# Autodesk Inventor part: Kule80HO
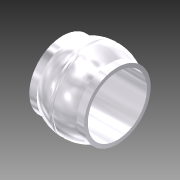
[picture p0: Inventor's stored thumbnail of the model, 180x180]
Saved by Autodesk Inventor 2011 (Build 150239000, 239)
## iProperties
Created: 2010-11
Document SubType Name: Modeling
Designer: tribel
Density: 1 g/cm^3
Author: tribel
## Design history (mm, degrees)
sketch "Sketch1"
  geometry: L1 (-51.8, 0)-(51.8, 0) reference; L2 (0, -11.888)-(0, 71.331) reference; L3 (-37, 45)-(-26.935, 45); L4 (-37, 45)-(-37, 0); L5 (-3, 0)-(-3, 52.359); L6 (-37, 40)-(-3, 40); L7 (37, 45)-(26.935, 45); L8 (37, 45)-(37, 0); L9 (37, 40)-(3, 40); L10 (3, 0)-(3, 52.359); L11 (-3, 40)-(3, 40); A1 r 7.692 centre (0, 59.442) between (-3, 52.359) and (3, 52.359); A2 r 52.445 centre (0, 0) between (26.935, 45) and (3, 52.359); A3 r 52.445 centre (0, 0) between (-3, 52.359) and (-26.935, 45)
  constraints: 18 end point, 7 symmetric about line, 6 point on circle, 6 point on line, 4 perpendicular, 3 centre point, 1 parallel
  dimensions: "d1" = 37 distance between parallel lines of L4 L2; "d2" = 3 distance between parallel lines of L5 L2; "d3" = 90 diameter of L3 L1; "d4" = 103.5 dimension on A1 L1; "d5" = 80 diameter of L9 L1; "d7" = 52.445 radius of A3
revolve "Revolution1" sketch "Sketch1" stored, may be unused: angle "d8" = 90 deg
body "Solid1"
other parameters: "d0" = 65.92, "d6" = 32.96
